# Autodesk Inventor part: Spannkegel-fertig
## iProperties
Created: 2008-01
Part Number: Spannkegel-fertig
Document SubType Name: Modeling
Designer: Olaf
Density: 7.1 g/cm^3
Material: Schmiedbares Eisen
Surface Area: 187.565 cm^2
Mass: 1011.62 g
Volume: 142.482 cm^3
Author: Olaf
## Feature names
1. Extrusion1
2. Extrusion2
3. Fase1 [Chamfer]
4. Trennen1
5. Trennen3
6. Trennen4
7. Trennen5
8. Trennen6
9. Spiegeln1 [Mirror]
10. Trennen7
11. Trennen8
12. Bohrung1 [Hole]
13. Bohrung2 [Hole]
14. Trennen11
15. Trennen12
16. Trennen13
17. Trennen14
18. Trennen15
19. Trennen16
